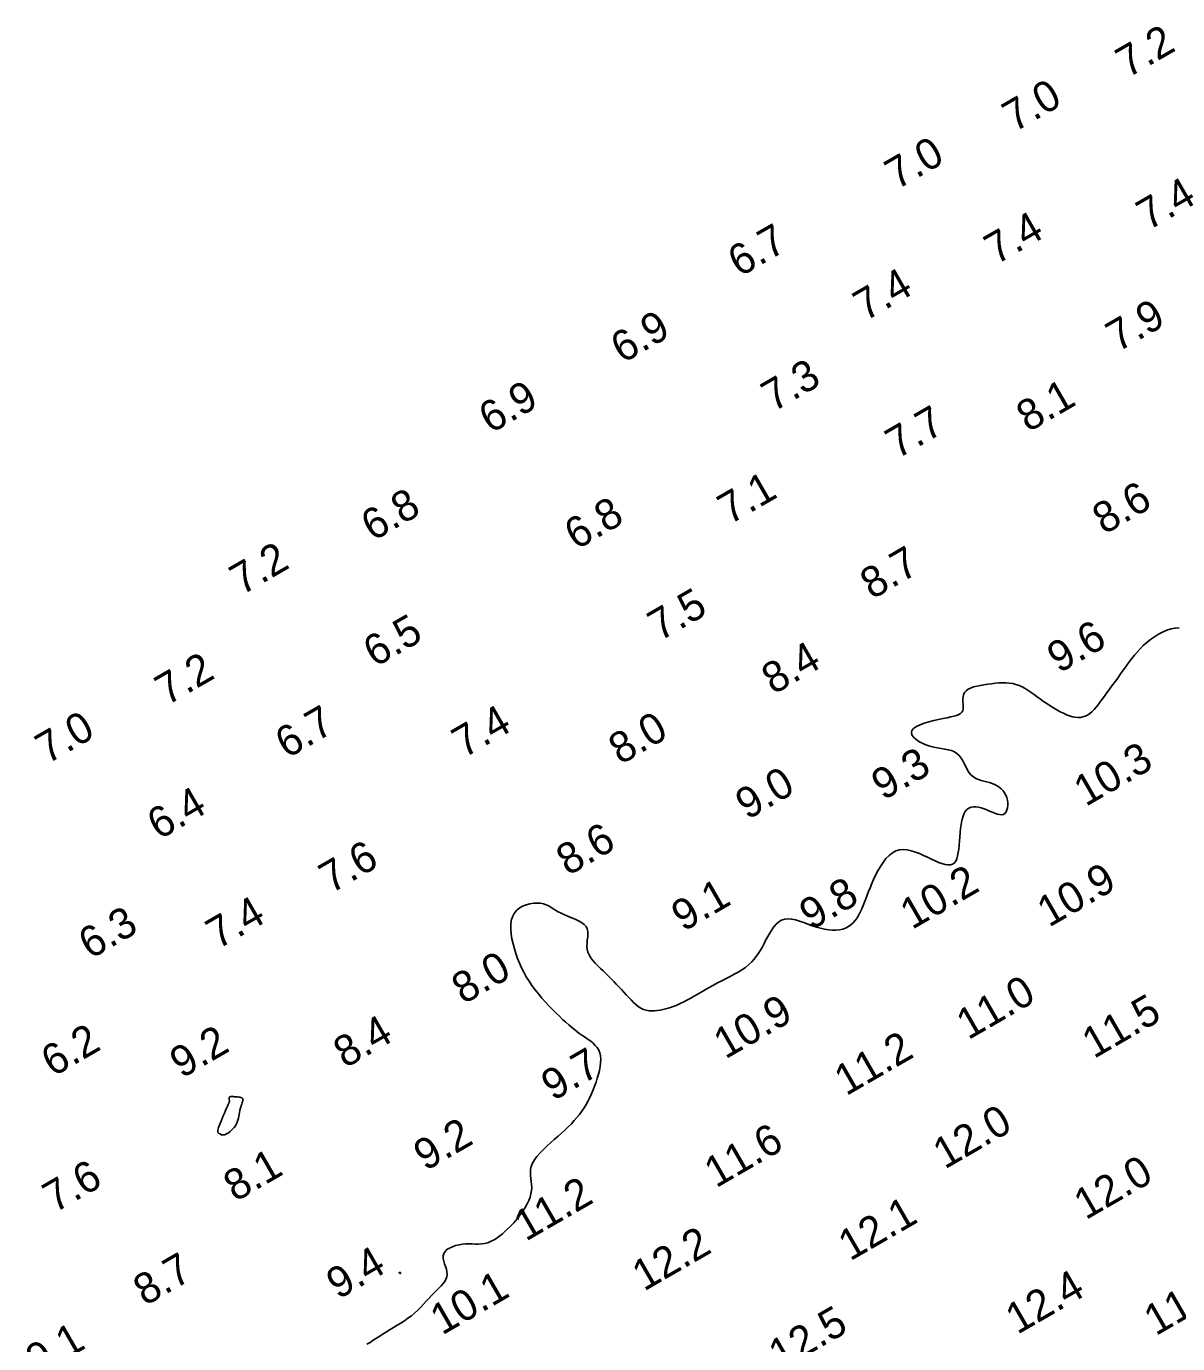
# Model space of a CAD drawing. Extents: x 3024098 to 3056816, y 418252 to 509144.
# Drawn here: x 3034924.8 to 3035111.8, y 419254.4 to 419468.4 of the extents above; entities that cross this region are included whole.
import ezdxf

# ---------------------------------------------------------------- set-up
doc = ezdxf.new("R2010")
doc.units = 0
doc.layers.add('V-CHAN-CONT-EL10', color=7, linetype='Continuous')
doc.layers.add('V-TOPO-SOUN-0911', color=7, linetype='Continuous')

msp = doc.modelspace()

# ---------------------------------------------------------------- linework, layer by layer
at = {"layer": 'V-CHAN-CONT-EL10'}
msp.add_lwpolyline([(3034980.1, 419254.33), (3034980.62, 419254.64), (3034981.14, 419254.98), (3034981.66, 419255.32), (3034982.19, 419255.67), (3034982.73, 419256.03), (3034983.29, 419256.37), (3034983.87, 419256.72), (3034984.46, 419257.06), (3034985.05, 419257.41), (3034985.64, 419257.78), (3034986.23, 419258.15), (3034986.79, 419258.55), (3034987.35, 419258.97), (3034987.87, 419259.41), (3034988.37, 419259.88), (3034988.85, 419260.36), (3034989.31, 419260.84), (3034989.76, 419261.32), (3034990.19, 419261.79), (3034990.61, 419262.25), (3034991.02, 419262.68), (3034991.42, 419263.09), (3034991.81, 419263.47), (3034992.17, 419263.83), (3034992.48, 419264.19), (3034992.75, 419264.54), (3034992.96, 419264.9), (3034993.09, 419265.27), (3034993.15, 419265.66), (3034993.11, 419266.07), (3034993.02, 419266.51), (3034992.88, 419266.95), (3034992.73, 419267.4), (3034992.6, 419267.84), (3034992.52, 419268.27), (3034992.51, 419268.67), (3034992.6, 419269.05), (3034992.81, 419269.39), (3034993.12, 419269.7), (3034993.53, 419269.96), (3034994.01, 419270.18), (3034994.53, 419270.36), (3034995.08, 419270.5), (3034995.65, 419270.6), (3034996.2, 419270.65), (3034996.73, 419270.66), (3034997.23, 419270.64), (3034997.73, 419270.61), (3034998.21, 419270.6), (3034998.71, 419270.62), (3034999.21, 419270.68), (3034999.74, 419270.82), (3035000.3, 419271.05), (3035000.89, 419271.37), (3035001.5, 419271.79), (3035002.13, 419272.29), (3035002.76, 419272.84), (3035003.38, 419273.44), (3035003.96, 419274.07), (3035004.52, 419274.7), (3035005.02, 419275.34), (3035005.46, 419275.95), (3035005.84, 419276.55), (3035006.16, 419277.12), (3035006.42, 419277.69), (3035006.62, 419278.23), (3035006.77, 419278.76), (3035006.85, 419279.28), (3035006.89, 419279.79), (3035006.87, 419280.28), (3035006.82, 419280.77), (3035006.76, 419281.25), (3035006.71, 419281.74), (3035006.68, 419282.22), (3035006.71, 419282.72), (3035006.82, 419283.22), (3035007.01, 419283.73), (3035007.32, 419284.27), (3035007.72, 419284.81), (3035008.2, 419285.36), (3035008.75, 419285.92), (3035009.33, 419286.48), (3035009.94, 419287.04), (3035010.56, 419287.59), (3035011.17, 419288.12), (3035011.75, 419288.64), (3035012.31, 419289.15), (3035012.83, 419289.65), (3035013.33, 419290.15), (3035013.8, 419290.65), (3035014.24, 419291.15), (3035014.65, 419291.66), (3035015.04, 419292.18), (3035015.4, 419292.72), (3035015.74, 419293.28), (3035016.05, 419293.84), (3035016.35, 419294.43), (3035016.62, 419295.02), (3035016.87, 419295.63), (3035017.11, 419296.25), (3035017.33, 419296.88), (3035017.54, 419297.52), (3035017.73, 419298.17), (3035017.88, 419298.8), (3035018, 419299.43), (3035018.08, 419300.04), (3035018.1, 419300.61), (3035018.06, 419301.16), (3035017.95, 419301.65), (3035017.77, 419302.1), (3035017.52, 419302.5), (3035017.21, 419302.87), (3035016.86, 419303.21), (3035016.47, 419303.53), (3035016.05, 419303.83), (3035015.61, 419304.14), (3035015.17, 419304.44), (3035014.72, 419304.76), (3035014.28, 419305.09), (3035013.83, 419305.44), (3035013.37, 419305.82), (3035012.9, 419306.21), (3035012.42, 419306.64), (3035011.91, 419307.1), (3035011.39, 419307.59), (3035010.84, 419308.12), (3035010.27, 419308.68), (3035009.69, 419309.28), (3035009.11, 419309.9), (3035008.54, 419310.55), (3035007.98, 419311.22), (3035007.44, 419311.9), (3035006.93, 419312.6), (3035006.45, 419313.3), (3035006.01, 419314.02), (3035005.61, 419314.75), (3035005.24, 419315.49), (3035004.9, 419316.24), (3035004.6, 419317), (3035004.32, 419317.78), (3035004.07, 419318.56), (3035003.86, 419319.36), (3035003.68, 419320.16), (3035003.55, 419320.95), (3035003.48, 419321.72), (3035003.48, 419322.45), (3035003.56, 419323.13), (3035003.74, 419323.75), (3035004.01, 419324.3), (3035004.39, 419324.77), (3035004.86, 419325.15), (3035005.4, 419325.46), (3035005.98, 419325.69), (3035006.58, 419325.85), (3035007.18, 419325.94), (3035007.76, 419325.97), (3035008.3, 419325.94), (3035008.78, 419325.84), (3035009.21, 419325.7), (3035009.6, 419325.52), (3035009.98, 419325.31), (3035010.36, 419325.07), (3035010.75, 419324.82), (3035011.18, 419324.57), (3035011.65, 419324.32), (3035012.19, 419324.08), (3035012.77, 419323.84), (3035013.36, 419323.61), (3035013.95, 419323.36), (3035014.5, 419323.1), (3035015, 419322.82), (3035015.42, 419322.52), (3035015.73, 419322.17), (3035015.92, 419321.79), (3035016, 419321.36), (3035016.02, 419320.92), (3035015.98, 419320.45), (3035015.92, 419319.96), (3035015.87, 419319.47), (3035015.86, 419318.98), (3035015.9, 419318.49), (3035016.03, 419318.02), (3035016.23, 419317.56), (3035016.51, 419317.11), (3035016.83, 419316.67), (3035017.21, 419316.24), (3035017.61, 419315.81), (3035018.04, 419315.38), (3035018.47, 419314.96), (3035018.91, 419314.53), (3035019.34, 419314.1), (3035019.78, 419313.68), (3035020.21, 419313.25), (3035020.63, 419312.82), (3035021.05, 419312.39), (3035021.46, 419311.96), (3035021.86, 419311.52), (3035022.25, 419311.09), (3035022.64, 419310.66), (3035023.03, 419310.25), (3035023.41, 419309.86), (3035023.8, 419309.51), (3035024.2, 419309.19), (3035024.61, 419308.93), (3035025.03, 419308.72), (3035025.46, 419308.58), (3035025.91, 419308.49), (3035026.37, 419308.46), (3035026.83, 419308.47), (3035027.29, 419308.51), (3035027.74, 419308.58), (3035028.19, 419308.68), (3035028.62, 419308.79), (3035029.04, 419308.9), (3035029.44, 419309.03), (3035029.85, 419309.16), (3035030.26, 419309.32), (3035030.68, 419309.5), (3035031.12, 419309.7), (3035031.58, 419309.92), (3035032.08, 419310.19), (3035032.61, 419310.48), (3035033.18, 419310.8), (3035033.78, 419311.15), (3035034.41, 419311.52), (3035035.06, 419311.89), (3035035.73, 419312.27), (3035036.4, 419312.65), (3035037.09, 419313.02), (3035037.78, 419313.38), (3035038.46, 419313.73), (3035039.14, 419314.08), (3035039.8, 419314.43), (3035040.43, 419314.78), (3035041.03, 419315.15), (3035041.59, 419315.54), (3035042.11, 419315.95), (3035042.57, 419316.38), (3035042.99, 419316.84), (3035043.37, 419317.32), (3035043.71, 419317.83), (3035044.04, 419318.35), (3035044.35, 419318.88), (3035044.64, 419319.43), (3035044.94, 419319.99), (3035045.24, 419320.56), (3035045.55, 419321.11), (3035045.88, 419321.65), (3035046.23, 419322.14), (3035046.61, 419322.58), (3035047.02, 419322.94), (3035047.48, 419323.21), (3035047.98, 419323.38), (3035048.52, 419323.42), (3035049.11, 419323.37), (3035049.74, 419323.24), (3035050.4, 419323.05), (3035051.07, 419322.81), (3035051.75, 419322.56), (3035052.44, 419322.31), (3035053.13, 419322.08), (3035053.81, 419321.89), (3035054.47, 419321.74), (3035055.11, 419321.64), (3035055.73, 419321.59), (3035056.31, 419321.59), (3035056.87, 419321.64), (3035057.4, 419321.76), (3035057.88, 419321.93), (3035058.32, 419322.16), (3035058.72, 419322.45), (3035059.09, 419322.79), (3035059.42, 419323.17), (3035059.73, 419323.59), (3035060.01, 419324.05), (3035060.26, 419324.53), (3035060.5, 419325.04), (3035060.73, 419325.56), (3035060.94, 419326.11), (3035061.16, 419326.67), (3035061.38, 419327.25), (3035061.61, 419327.85), (3035061.85, 419328.48), (3035062.12, 419329.14), (3035062.42, 419329.82), (3035062.75, 419330.52), (3035063.12, 419331.23), (3035063.52, 419331.93), (3035063.96, 419332.59), (3035064.43, 419333.2), (3035064.93, 419333.73), (3035065.47, 419334.15), (3035066.04, 419334.46), (3035066.63, 419334.63), (3035067.25, 419334.68), (3035067.9, 419334.62), (3035068.55, 419334.48), (3035069.21, 419334.27), (3035069.87, 419334.01), (3035070.53, 419333.72), (3035071.18, 419333.41), (3035071.81, 419333.12), (3035072.41, 419332.84), (3035072.99, 419332.59), (3035073.53, 419332.39), (3035074.04, 419332.24), (3035074.49, 419332.17), (3035074.9, 419332.18), (3035075.25, 419332.28), (3035075.53, 419332.48), (3035075.76, 419332.79), (3035075.94, 419333.18), (3035076.07, 419333.64), (3035076.18, 419334.17), (3035076.26, 419334.76), (3035076.33, 419335.38), (3035076.38, 419336.04), (3035076.43, 419336.73), (3035076.49, 419337.42), (3035076.56, 419338.1), (3035076.65, 419338.76), (3035076.77, 419339.38), (3035076.91, 419339.94), (3035077.09, 419340.44), (3035077.31, 419340.85), (3035077.58, 419341.16), (3035077.9, 419341.39), (3035078.25, 419341.53), (3035078.64, 419341.6), (3035079.05, 419341.6), (3035079.48, 419341.54), (3035079.92, 419341.44), (3035080.37, 419341.29), (3035080.82, 419341.12), (3035081.27, 419340.93), (3035081.71, 419340.74), (3035082.12, 419340.57), (3035082.52, 419340.43), (3035082.88, 419340.35), (3035083.21, 419340.33), (3035083.5, 419340.39), (3035083.74, 419340.55), (3035083.94, 419340.79), (3035084.08, 419341.1), (3035084.18, 419341.46), (3035084.23, 419341.86), (3035084.22, 419342.28), (3035084.17, 419342.71), (3035084.06, 419343.12), (3035083.9, 419343.52), (3035083.7, 419343.88), (3035083.45, 419344.22), (3035083.16, 419344.52), (3035082.83, 419344.8), (3035082.47, 419345.04), (3035082.08, 419345.25), (3035081.67, 419345.42), (3035081.23, 419345.56), (3035080.78, 419345.68), (3035080.33, 419345.79), (3035079.88, 419345.91), (3035079.44, 419346.05), (3035079.02, 419346.23), (3035078.63, 419346.47), (3035078.28, 419346.77), (3035077.97, 419347.15), (3035077.69, 419347.59), (3035077.44, 419348.07), (3035077.18, 419348.56), (3035076.92, 419349.06), (3035076.64, 419349.52), (3035076.33, 419349.94), (3035075.97, 419350.29), (3035075.55, 419350.55), (3035075.08, 419350.74), (3035074.56, 419350.88), (3035074.01, 419350.98), (3035073.42, 419351.07), (3035072.81, 419351.17), (3035072.19, 419351.28), (3035071.55, 419351.44), (3035070.92, 419351.66), (3035070.31, 419351.93), (3035069.76, 419352.24), (3035069.28, 419352.58), (3035068.9, 419352.94), (3035068.65, 419353.31), (3035068.56, 419353.67), (3035068.64, 419354.02), (3035068.92, 419354.35), (3035069.38, 419354.65), (3035069.97, 419354.93), (3035070.65, 419355.18), (3035071.41, 419355.41), (3035072.19, 419355.61), (3035072.97, 419355.79), (3035073.7, 419355.95), (3035074.37, 419356.08), (3035074.96, 419356.2), (3035075.47, 419356.32), (3035075.9, 419356.44), (3035076.27, 419356.58), (3035076.55, 419356.75), (3035076.76, 419356.96), (3035076.9, 419357.21), (3035076.96, 419357.52), (3035076.98, 419357.87), (3035076.96, 419358.25), (3035076.94, 419358.65), (3035076.92, 419359.06), (3035076.95, 419359.45), (3035077.03, 419359.82), (3035077.19, 419360.16), (3035077.44, 419360.45), (3035077.78, 419360.7), (3035078.19, 419360.9), (3035078.67, 419361.08), (3035079.2, 419361.22), (3035079.77, 419361.34), (3035080.35, 419361.44), (3035080.96, 419361.53), (3035081.56, 419361.61), (3035082.15, 419361.68), (3035082.75, 419361.73), (3035083.33, 419361.75), (3035083.91, 419361.75), (3035084.47, 419361.71), (3035085.02, 419361.62), (3035085.55, 419361.49), (3035086.06, 419361.31), (3035086.56, 419361.09), (3035087.05, 419360.82), (3035087.53, 419360.52), (3035088.02, 419360.19), (3035088.5, 419359.85), (3035089, 419359.48), (3035089.51, 419359.12), (3035090.03, 419358.74), (3035090.57, 419358.38), (3035091.11, 419358.02), (3035091.66, 419357.68), (3035092.21, 419357.35), (3035092.75, 419357.06), (3035093.27, 419356.8), (3035093.78, 419356.57), (3035094.27, 419356.39), (3035094.74, 419356.25), (3035095.19, 419356.16), (3035095.62, 419356.12), (3035096.03, 419356.13), (3035096.43, 419356.2), (3035096.81, 419356.32), (3035097.18, 419356.5), (3035097.54, 419356.75), (3035097.9, 419357.05), (3035098.24, 419357.39), (3035098.58, 419357.78), (3035098.91, 419358.2), (3035099.25, 419358.64), (3035099.58, 419359.11), (3035099.93, 419359.58), (3035100.27, 419360.06), (3035100.63, 419360.54), (3035100.98, 419361.03), (3035101.35, 419361.53), (3035101.71, 419362.03), (3035102.08, 419362.53), (3035102.44, 419363.04), (3035102.81, 419363.56), (3035103.18, 419364.09), (3035103.56, 419364.62), (3035103.95, 419365.15), (3035104.35, 419365.69), (3035104.78, 419366.22), (3035105.23, 419366.75), (3035105.72, 419367.28), (3035106.24, 419367.79), (3035106.81, 419368.3), (3035107.42, 419368.79), (3035108.05, 419369.24), (3035108.71, 419369.65), (3035109.38, 419370), (3035110.06, 419370.29), (3035110.74, 419370.51), (3035111.4, 419370.63), (3035112.06, 419370.66)], dxfattribs=at)
for points in [[(3034957.03, 419288.37), (3034956.87, 419288.33), (3034956.72, 419288.32), (3034956.6, 419288.34), (3034956.49, 419288.36), (3034956.4, 419288.4), (3034956.32, 419288.44), (3034956.25, 419288.48), (3034956.19, 419288.51), (3034956.13, 419288.54), (3034956.09, 419288.57), (3034956.05, 419288.59), (3034956.01, 419288.61), (3034955.98, 419288.64), (3034955.96, 419288.66), (3034955.93, 419288.7), (3034955.91, 419288.74), (3034955.89, 419288.8), (3034955.89, 419288.88), (3034955.89, 419288.98), (3034955.92, 419289.12), (3034955.96, 419289.31), (3034956.03, 419289.54), (3034956.14, 419289.83), (3034956.27, 419290.18), (3034956.43, 419290.57), (3034956.61, 419291), (3034956.79, 419291.44), (3034956.98, 419291.87), (3034957.17, 419292.29), (3034957.33, 419292.67), (3034957.47, 419293), (3034957.58, 419293.26), (3034957.66, 419293.46), (3034957.72, 419293.61), (3034957.76, 419293.73), (3034957.78, 419293.81), (3034957.78, 419293.88), (3034957.78, 419293.93), (3034957.77, 419293.99), (3034957.76, 419294.05), (3034957.75, 419294.12), (3034957.74, 419294.19), (3034957.73, 419294.27), (3034957.74, 419294.34), (3034957.75, 419294.41), (3034957.78, 419294.47), (3034957.82, 419294.51), (3034957.88, 419294.54), (3034957.96, 419294.56), (3034958.05, 419294.57), (3034958.16, 419294.57), (3034958.28, 419294.56), (3034958.42, 419294.55), (3034958.58, 419294.54), (3034958.75, 419294.52), (3034958.93, 419294.51), (3034959.12, 419294.49), (3034959.3, 419294.47), (3034959.48, 419294.44), (3034959.64, 419294.4), (3034959.78, 419294.34), (3034959.89, 419294.27), (3034959.96, 419294.17), (3034959.99, 419294.05), (3034959.97, 419293.9), (3034959.93, 419293.73), (3034959.86, 419293.54), (3034959.78, 419293.32), (3034959.69, 419293.09), (3034959.61, 419292.84), (3034959.53, 419292.57), (3034959.46, 419292.28), (3034959.4, 419291.98), (3034959.35, 419291.67), (3034959.3, 419291.36), (3034959.23, 419291.04), (3034959.15, 419290.73), (3034959.04, 419290.42), (3034958.91, 419290.12), (3034958.75, 419289.83), (3034958.55, 419289.56), (3034958.34, 419289.31), (3034958.11, 419289.08), (3034957.88, 419288.87), (3034957.64, 419288.69), (3034957.42, 419288.55), (3034957.21, 419288.44)], [(3034985.43, 419265.91), (3034985.43, 419265.91), (3034985.43, 419265.92), (3034985.43, 419265.92), (3034985.43, 419265.92), (3034985.42, 419265.93), (3034985.42, 419265.93), (3034985.41, 419265.94), (3034985.4, 419265.94), (3034985.39, 419265.95), (3034985.38, 419265.96), (3034985.37, 419265.97), (3034985.36, 419265.97), (3034985.36, 419265.98), (3034985.35, 419265.99), (3034985.36, 419266), (3034985.37, 419266), (3034985.38, 419266.01), (3034985.39, 419266.01), (3034985.41, 419266.01), (3034985.43, 419266.01), (3034985.45, 419266.02), (3034985.48, 419266.01), (3034985.5, 419266.01), (3034985.51, 419266.01), (3034985.53, 419266), (3034985.54, 419266), (3034985.55, 419265.99), (3034985.56, 419265.98), (3034985.57, 419265.97), (3034985.57, 419265.96), (3034985.58, 419265.94), (3034985.58, 419265.92), (3034985.58, 419265.9), (3034985.57, 419265.88), (3034985.57, 419265.86), (3034985.56, 419265.84), (3034985.55, 419265.82), (3034985.54, 419265.8), (3034985.53, 419265.79), (3034985.52, 419265.79), (3034985.51, 419265.79), (3034985.5, 419265.79), (3034985.49, 419265.8), (3034985.47, 419265.81), (3034985.46, 419265.82), (3034985.45, 419265.83), (3034985.45, 419265.84), (3034985.44, 419265.85), (3034985.44, 419265.86), (3034985.43, 419265.87), (3034985.43, 419265.88), (3034985.43, 419265.89), (3034985.43, 419265.9), (3034985.43, 419265.9), (3034985.43, 419265.91)]]:
    msp.add_lwpolyline(points, close=True, dxfattribs=at)

# ---------------------------------------------------------------- texts
at = {"layer": 'V-TOPO-SOUN-0911'}
for s, p in [('7.2', (3035103.69, 419459.89)), ('7.0', (3035085.27, 419451.09)), ('7.0', (3035066.18, 419441.74)), ('7.4', (3035107.04, 419435.12)), ('7.4', (3035082.33, 419429.57)), ('6.7', (3035040.67, 419427.57)), ('7.4', (3035061.04, 419420.39)), ('7.9', (3035102.08, 419415.37)), ('6.9', (3035021.64, 419413.53)), ('7.3', (3035046.11, 419405.66)), ('6.9', (3035000.21, 419402.15)), ('8.1', (3035087.53, 419402.36)), ('7.7', (3035066.26, 419398.04)), ('7.1', (3035039.01, 419387.36)), ('6.8', (3034981.09, 419384.66)), ('8.6', (3035099.88, 419385.75)), ('6.8', (3035014.12, 419383.25)), ('7.2', (3034959.76, 419375.9)), ('8.7', (3035062.16, 419375.21)), ('7.5', (3035027.66, 419368.42)), ('6.5', (3034981.44, 419364.19)), ('9.6', (3035092.53, 419363.21)), ('8.4', (3035046.15, 419359.76)), ('7.2', (3034947.62, 419357.99)), ('7.0', (3034928.18, 419348.47)), ('6.7', (3034967.14, 419349.36)), ('7.4', (3034995.85, 419349.46)), ('8.0', (3035021.29, 419348.37)), ('9.3', (3035063.99, 419342.57)), ('10.3 ', (3035096.87, 419341.57)), ('9.0', (3035041.9, 419339.41)), ('6.4', (3034946.34, 419336.17)), ('8.6', (3035012.78, 419330.33)), ('7.6', (3034974.26, 419327.45)), ('10.2 ', (3035068.65, 419321.59)), ('10.9 ', (3035090.9, 419321.96)), ('9.1', (3035031.5, 419321.25)), ('9.8', (3035052.28, 419321.5)), ('7.4', (3034955.89, 419318.39)), ('6.3', (3034935.19, 419316.78)), ('8.0', (3034995.8, 419309.46)), ('11.0 ', (3035077.79, 419303.68)), ('10.9 ', (3035038.34, 419300.56)), ('11.5 ', (3035098.2, 419300.63)), ('8.4', (3034976.59, 419299.09)), ('6.2', (3034929.12, 419297.68)), ('9.2', (3034950.02, 419297.42)), ('11.2 ', (3035057.96, 419294.59)), ('9.7', (3035010.35, 419293.75)), ('12.0 ', (3035073.98, 419282.68)), ('9.2', (3034989.62, 419282.39)), ('11.6 ', (3035036.83, 419279.64)), ('7.6', (3034929.38, 419275.58)), ('8.1', (3034958.73, 419277.39)), ('12.0 ', (3035096.88, 419274.45)), ('11.2 ', (3035005.92, 419270.97)), ('12.1 ', (3035058.6, 419267.77)), ('12.2 ', (3035025.12, 419262.87)), ('8.7', (3034944.08, 419260.48)), ('9.4', (3034975.44, 419261.53)), ('10.1 ', (3034992.32, 419255.73)), ('12.4 ', (3035085.78, 419255.85)), ('11.6 ', (3035108.25, 419255.62)), ('12.5 ', (3035047.28, 419250.01)), ('9.1', (3034926.61, 419249.17))]:
    msp.add_text(s, height=5, rotation=30, dxfattribs=at).set_placement(p)

doc.saveas('drawing.dxf')
